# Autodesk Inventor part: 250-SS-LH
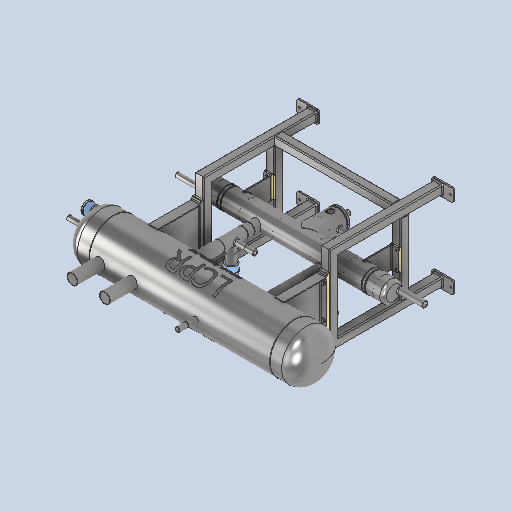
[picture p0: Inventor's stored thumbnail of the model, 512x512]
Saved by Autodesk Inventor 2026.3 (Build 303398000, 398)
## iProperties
Created: 2026-05
Part Number: 250-SS-LH
Material: Generic
Document SubType Name: Modeling
Designer: rva
Density: 1 g/cm^3
Appearance: Default
Author: rva
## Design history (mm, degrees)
derived "250-SS-LH.iam"
body "Solid1"
node "LCPR-SS-100- Sub Cooler.iam:1::ISO 5251 Equal Tee DN100 3.6 "
node "LCPR-SS-100- Sub Cooler.iam:1::ISO 5251 Reducing Tee DN100 x"
node "LCPR-SS-100- Sub Cooler.iam:1::ISO 5251 Reducing Tee DN100 x"
node "LCPR-SS-100- Sub Cooler.iam:1::SS-100-14 hole Sub Cooler Pla"
node "LCPR-SS-100- Sub Cooler.iam:1::SS-100-14 hole Sub Cooler Pla"
node "LCPR-SS-100- Sub Cooler.iam:1::100 mm Subcooler Leg.ipt:1"
node "LCPR-SS-100- Sub Cooler.iam:1::LCPR-SS-100 Blank Plate.ipt:1"
node "LCPR-SS-100- Sub Cooler.iam:1::100 mm Subcooler Leg.ipt:2"
node "LCPR-SS-100- Sub Cooler.iam:1::1-2 Inch NPT Socket - SS.ipt:"
node "LCPR-SS-100- Sub Cooler.iam:1::H1100-R.ipt:1"
node "LCPR-SS-100- Sub Cooler.iam:1::H1100-R.ipt:2"
node "LCPR-SS-100- Sub Cooler.iam:1::1-2 Inch NPT Socket - SS.ipt:"
node "LCPR-SS-100- Sub Cooler.iam:1::1-2 Inch NPT Socket - SS.ipt:"
node "LCPR-SS-100- Sub Cooler.iam:1::Welds"
node "LCPR-SS-250-Frame Assembly.iam:2::LCPR-SS-250-120 x 70 Frame"
node "LCPR-SS-250-Frame Assembly.iam:2::LCPR-SS-250-120 x 70 Frame"
node "LCPR-SS-250-Frame Assembly.iam:2::LCPR-SS-250-120 x 70 Frame"
node "LCPR-SS-250-Frame Assembly.iam:2::LCPR-SS-250-120 x 70 Frame"
node "LCPR-SS-250-Frame Assembly.iam:2::Welds"
node "Nylon Heat Tranfer Spacer 276.5x50.ipt:1"
node "Nylon Heat Tranfer Spacer 276.5x50.ipt:2"
node "AS 1111 - Metric M10 x 80:1"
node "AS 1112 (4) - Metric M10:1"
node "AS 1237 (4.1) 10 mm:1"
node "AS 1237 (4.1) 10 mm:2"
node "AS 1111 - Metric M10 x 80:2"
node "AS 1112 (4) - Metric M10:2"
node "AS 1237 (4.1) 10 mm:3"
node "AS 1237 (4.1) 10 mm:4"
node "AS 1111 - Metric M10 x 80:3"
node "AS 1112 (4) - Metric M10:3"
node "AS 1237 (4.1) 10 mm:5"
node "AS 1237 (4.1) 10 mm:6"
node "AS 1111 - Metric M10 x 80:4"
node "AS 1112 (4) - Metric M10:4"
node "AS 1237 (4.1) 10 mm:7"
node "AS 1237 (4.1) 10 mm:8"
node "250-SS-SHELL-WELD.iam:1::ASME B36.10M Pipe 10.75 x 0.165 - 3"
node "250-SS-SHELL-WELD.iam:1::LCPR-LOGO.ipt:1"
node "250-SS-SHELL-WELD.iam:1::LCPR-SS-250 mm Dome End Cap.ipt:1"
node "250-SS-SHELL-WELD.iam:1::ANSI/ASME B36.19M Pipe 2 - Schedule"
node "250-SS-SHELL-WELD.iam:1::H1100-R.ipt:1"
node "250-SS-SHELL-WELD.iam:1::LCPR-SS-250-Leg Assembly.iam:1::Wel"
node "250-SS-SHELL-WELD.iam:1::LCPR-SS-250-Leg Assembly.iam:2::Wel"
node "250-SS-SHELL-WELD.iam:1::LCPR-SS-250 mm Dome End Cap.ipt:2"
node "Nylon Heat Tranfer Spacer 120x50.ipt:1"
node "Nylon Heat Tranfer Spacer 120x50.ipt:2"
node "250-SS-LH.iam_Bodies"
